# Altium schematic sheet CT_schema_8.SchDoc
size 277 x 170 mm
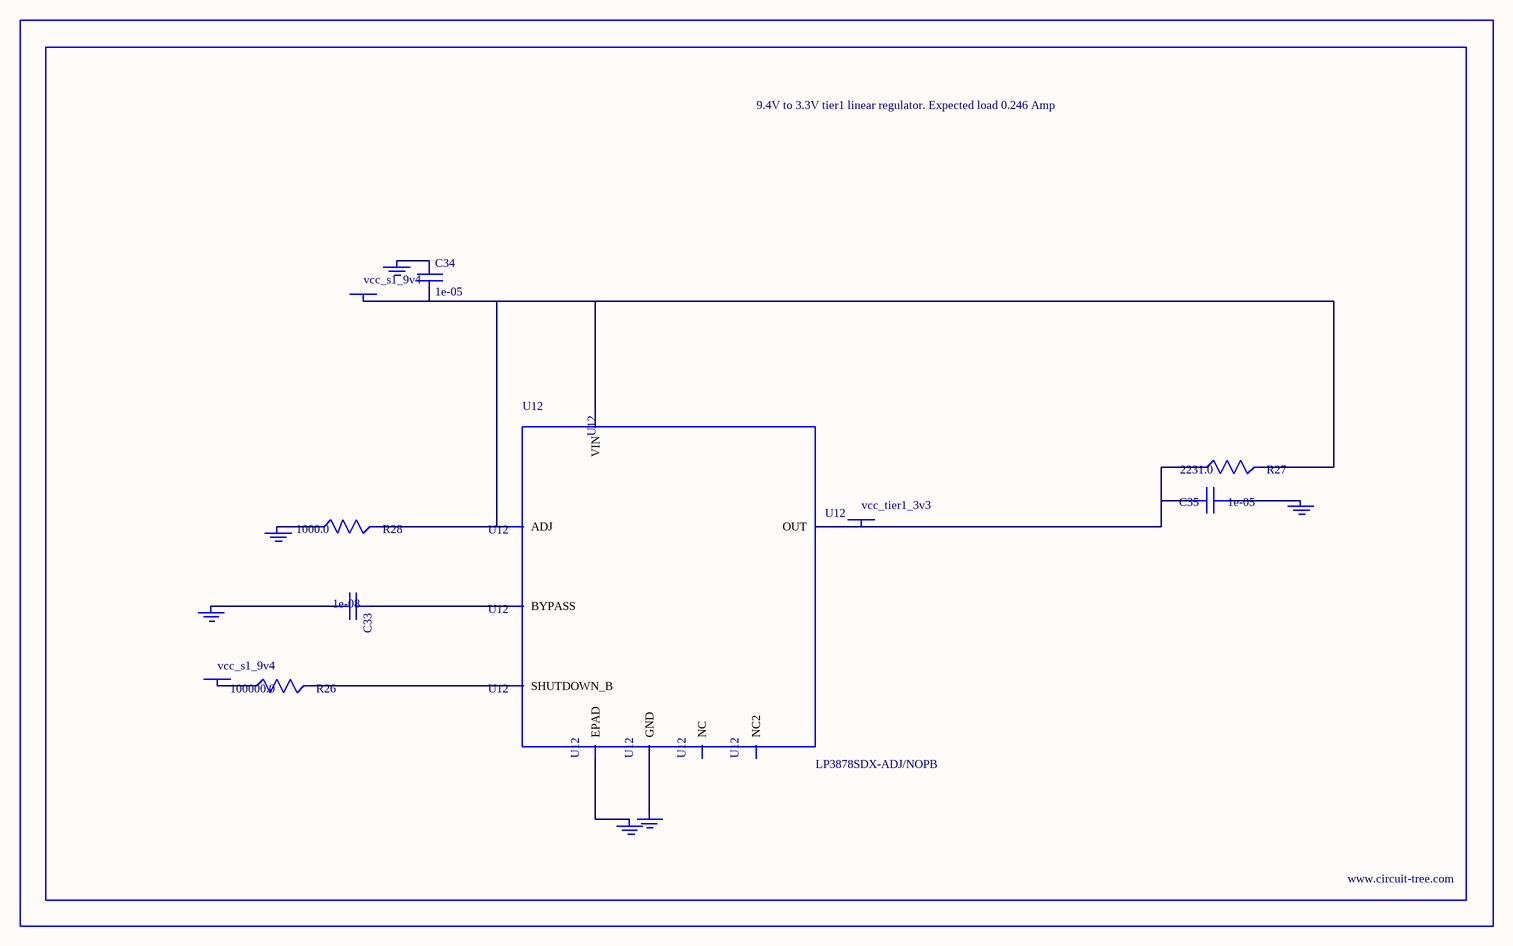
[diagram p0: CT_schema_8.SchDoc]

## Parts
BORDER7  (no value)
C33  1e-08  [C0402]
C34  1e-05  [C1206]
C35  1e-05  [C1210]
GND_INSTANCE_7_0  (no value)
GND_INSTANCE_7_1  (no value)
GND_INSTANCE_7_2  (no value)
GND_INSTANCE_7_3  (no value)
GND_INSTANCE_7_4  (no value)
GND_INSTANCE_7_5  (no value)
POWER_INSTANCE_7_0  vcc_s1_9v4
POWER_INSTANCE_7_1  vcc_s1_9v4
POWER_INSTANCE_7_2  vcc_tier1_3v3
R26  100000.0  [R0603]
R27  2231.0  [R0603]
R28  1000.0  [R0603]
U12  LP3878SDX-ADJ/NOPB  [WSON-8]

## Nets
NetC33_1: C33.1 U12.1(BYPASS)
NetC33_2: C33.2 GND_INSTANCE_7_0.0(GND)
NetC34_1: C34.1 GND_INSTANCE_7_1.0(GND)
NetC34_2: C34.2 POWER_INSTANCE_7_0.0(PWR) R27.2 R28.2 U12.4(VIN) U12.6(ADJ)
NetC35_1: C35.1 GND_INSTANCE_7_2.0(GND)
NetC35_2: C35.2 POWER_INSTANCE_7_2.0(PWR) R27.1 U12.5(OUT)
NetGND_INSTANCE_7_3_0: GND_INSTANCE_7_3.0(GND) R28.1
NetGND_INSTANCE_7_4_0: GND_INSTANCE_7_4.0(GND) U12.PAD(EPAD)
NetGND_INSTANCE_7_5_0: GND_INSTANCE_7_5.0(GND) U12.3(GND)
NetPOWER_INSTANCE_7_1_0: POWER_INSTANCE_7_1.0(PWR) R26.1
NetR26_2: R26.2 U12.8(SHUTDOWN_B)

Not connected (* = marked no-connect by the designer): U12 2(NC) 7(NC2)

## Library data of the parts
BORDER7 = BORDER_PAGE7
C33 = C0402C103K3RAC
C34 = C1206C106K3RACTU
C35 = GRM32DR61E106MA12L
GND_INSTANCE_7_0-GND_INSTANCE_7_5 = GND
POWER_INSTANCE_7_0-POWER_INSTANCE_7_2 = PWR
R26 = RC0603JR-07100KL
R27 = R27
R28 = RC0603JR-071KL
